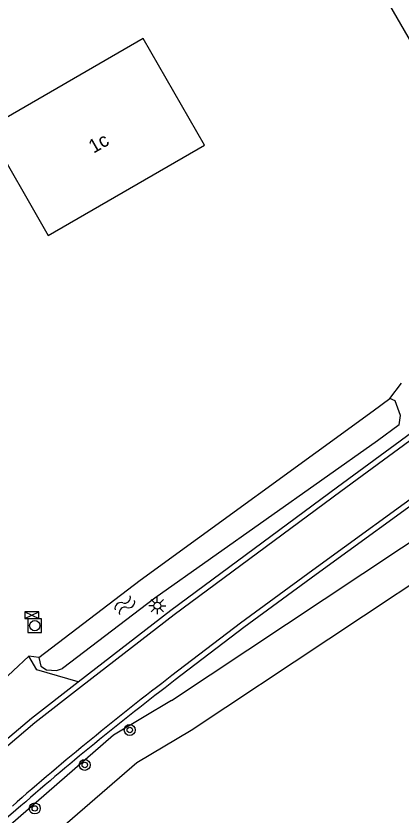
# Model space of a CAD drawing. Extents: x 136000 to 141000, y 400494 to 402006.
# Drawn here: x 138117.6 to 138145.6, y 401308.9 to 401367 of the extents above; entities that cross this region are included whole.
import ezdxf

# ---------------------------------------------------------------- set-up
doc = ezdxf.new("R2010")
doc.units = 0
for name, color, linetype in [('gg-afsc-lijn draadraster', 7, 'Continuous'), ('gg-anno-huisnummerreeks BGT', 7, 'Continuous'), ('gg-bbg-hoofdgebouw', 7, 'Continuous'), ('gg-knt-verharding', 7, 'Continuous'), ('gg-kntw-bovenkant insteek waterloop', 7, 'Continuous'), ('gt-grn-groengrens NZ', 7, 'Continuous'), ('gt-symb-boom', 7, 'Continuous'), ('gt-symb-lichtmast', 7, 'Continuous'), ('gt-symb-rioolkast', 7, 'Continuous'), ('gt-symb-rioolschacht', 7, 'Continuous'), ('gt-symb-watersymbool', 7, 'Continuous')]:
    doc.layers.add(name, color=color, linetype=linetype)

# ---------------------------------------------------------------- blocks, each defined once
blk = doc.blocks.new('gt0-RS')
at = {"layer": 'gt-symb-rioolschacht'}
blk.add_lwpolyline([(-0.5, -0.5), (0.5, -0.5), (0.5, 0.5), (-0.5, 0.5)], close=True, dxfattribs=at)
blk.add_circle((0, 0), 0.375, dxfattribs=at)
blk = doc.blocks.new('gt0-RKAST')
at = {"layer": 'gt-symb-rioolkast'}
for p, q in [((-0.501, -0.249), (0.501, 0.249)), ((-0.501, 0.249), (0.501, -0.249))]:
    blk.add_line(p, q, dxfattribs=at)
blk.add_lwpolyline([(0.501, 0.249), (-0.501, 0.249), (-0.501, -0.249), (0.501, -0.249)], close=True, dxfattribs=at)
blk = doc.blocks.new('gt0-LMAST')
at = {"layer": 'gt-symb-lichtmast'}
for p, q in [((-0.005, 0.246), (-0.005, 0.621)), ((-0.182, 0.173), (-0.447, 0.438)), ((0.172, 0.173), (0.437, 0.438)), ((-0.255, -0.004), (-0.63, -0.004)), ((-0.182, -0.181), (-0.447, -0.446)), ((-0.005, -0.254), (-0.005, -0.629)), ((0.437, -0.446), (0.172, -0.181)), ((0.245, -0.004), (0.62, -0.004))]:
    blk.add_line(p, q, dxfattribs=at)
blk.add_circle((-0.005, -0.004), 0.25, dxfattribs=at)
blk = doc.blocks.new('gt0-WA')
at = {"layer": 'gt-symb-watersymbool'}
for centre, start, end in [((-0.323, 0.022), 28.07249, 151.92751), ((0.427, 0.422), 208.07248, 331.92751), ((-0.323, -0.428), 28.07249, 151.92751), ((0.427, -0.028), 208.07248, 331.92751)]:
    blk.add_arc(centre, 0.425, start, end, dxfattribs=at)
blk = doc.blocks.new('gt0-BOOM')
at = {"layer": 'gt-symb-boom'}
for radius in [0.4, 0.2]:
    blk.add_circle((0, 0), radius, dxfattribs=at)

msp = doc.modelspace()

# ---------------------------------------------------------------- linework, layer by layer
at = {"layer": 'gg-afsc-lijn draadraster'}
msp.add_lwpolyline([(138156.3, 401347.995), (138132.548, 401389.049), (138133.352, 401389.854), (138135.368, 401394.991), (138130.875, 401401.374), (138160.184, 401423.209), (138176.823, 401433.702)], dxfattribs=at)
at = {"layer": 'gg-bbg-hoofdgebouw'}
msp.add_lwpolyline([(138119.936, 401351.061), (138131.332, 401357.629), (138126.863, 401365.391), (138115.467, 401358.823), (138119.936, 401351.061)], dxfattribs=at)
at = {"layer": 'gg-knt-verharding'}
msp.add_line((138118.531, 401320.428), (138114.736, 401316.879), dxfattribs=at)
for points in [[(138080.653, 401281.67), (138092.97, 401292.944), (138100.712, 401299.936), (138103.943, 401302.795), (138115.016, 401312.256), (138118.976, 401315.602), (138122.365, 401318.254), (138129.12, 401323.474), (138141.244, 401332.436), (138146.635, 401336.391), (138151.119, 401339.742), (138153.799, 401341.828), (138158.341, 401345.632), (138158.084, 401345.938)], [(138155.858, 401339.009), (138148.163, 401333.205), (138139.215, 401326.703), (138133.941, 401322.832), (138128.952, 401319.017)], [(138156.119, 401338.706), (138148.401, 401332.883), (138139.451, 401326.38), (138134.181, 401322.512), (138129.197, 401318.701)], [(138122.12, 401318.569), (138128.879, 401323.793), (138141.007, 401332.759), (138146.396, 401336.712)], [(138122.12, 401318.569), (138119.106, 401319.438), (138118.531, 401320.428)], [(138114.759, 401312.562), (138118.723, 401315.911), (138122.12, 401318.569)], [(138117.598, 401309.219), (138103.789, 401297.296), (138097.116, 401291.47), (138090.527, 401285.541), (138088.61, 401283.771), (138079.959, 401275.442)]]:
    msp.add_lwpolyline(points, dxfattribs=at)
for centre, radius, start, end in [((138260.091, 401146.744), 216.508, 127.27942, 131.24994), ((138260.18, 401146.639), 216.245, 127.28033, 131.25059)]:
    msp.add_arc(centre, radius, start, end, dxfattribs=at)
at = {"layer": 'gg-kntw-bovenkant insteek waterloop'}
for points in [[(138128.923, 401317.2), (138156.78, 401335.702), (138169.358, 401340.997)], [(138119.274, 401320.346), (138126.635, 401325.963), (138143.609, 401338.29), (138144.811, 401339.195)], [(138145.506, 401337.271), (138145.604, 401337.956), (138145.21, 401339.029), (138144.811, 401339.195)], [(138145.506, 401337.271), (138143.929, 401336.108), (138127.699, 401324.647), (138120.98, 401319.528)], [(138073.491, 401264.335), (138079.93, 401271.188), (138085.49, 401276.609), (138117.387, 401304.912), (138126.398, 401312.702), (138130.361, 401315.034), (138150.4, 401328.344)], [(138119.274, 401320.346), (138119.401, 401319.702), (138119.816, 401319.433), (138120.544, 401319.384), (138120.98, 401319.528)], [(138128.923, 401317.2), (138124.698, 401314.669), (138115.658, 401306.853), (138083.711, 401278.506), (138078.081, 401273.016), (138071.597, 401266.116)]]:
    msp.add_lwpolyline(points, dxfattribs=at)
at = {"layer": 'gt-grn-groengrens NZ'}
for p, q in [((138144.811, 401339.195), (138145.662, 401340.319)), ((138119.274, 401320.346), (138118.531, 401320.428))]:
    msp.add_line(p, q, dxfattribs=at)

# ---------------------------------------------------------------- block references
at = {"layer": 'gt-symb-boom'}
for p in [(138125.883, 401315.057), (138122.606, 401312.514), (138118.968, 401309.345)]:
    msp.add_blockref('gt0-BOOM', p, dxfattribs=at)
at = {"layer": 'gt-symb-lichtmast'}
msp.add_blockref('gt0-LMAST', (138127.895, 401324.111), dxfattribs=at)
at = {"layer": 'gt-symb-rioolkast'}
msp.add_blockref('gt0-RKAST', (138118.751, 401323.421), dxfattribs=at)
at = {"layer": 'gt-symb-rioolschacht'}
msp.add_blockref('gt0-RS', (138118.965, 401322.653), dxfattribs=at)
at = {"layer": 'gt-symb-watersymbool', "rotation": 42.6899577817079}
msp.add_blockref('gt0-WA', (138125.482, 401324.112), dxfattribs=at)

# ---------------------------------------------------------------- texts
at = {"layer": 'gg-anno-huisnummerreeks BGT'}
msp.add_text('1c', height=1, rotation=30, dxfattribs=at).set_placement((138123.248, 401357.009))

doc.saveas('drawing.dxf')
